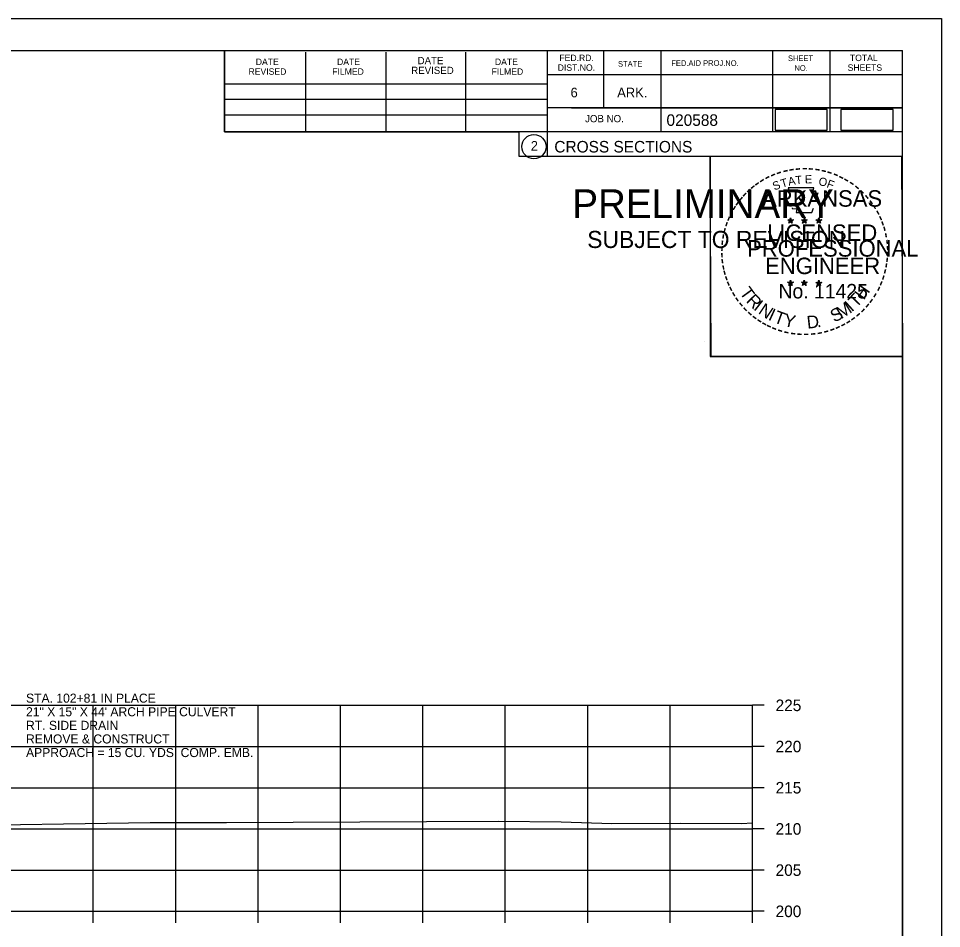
# Model space of a CAD drawing. Extents: x 1368968 to 1369915, y 377395 to 380381.
# Drawn here: x 1369189.1 to 1369301.1, y 378150.6 to 378261 of the extents above; entities that cross this region are included whole.
import ezdxf

# ---------------------------------------------------------------- set-up
doc = ezdxf.new("R2010")
doc.units = 0
for name, color, linetype in [('Default', 7, 'Continuous'), ('S_BREAKLINE_ANNOT', 7, 'Continuous'), ('S_BRIDGE', 7, 'Continuous'), ('S_BRIDGE_ANNOT', 7, 'Continuous'), ('S_BUILDING_ANNOT', 7, 'Continuous'), ('S_CAL_CORNER', 7, 'Continuous'), ('S_CTL_TABLE', 7, 'Continuous'), ('S_DITCHLINE_ANNOT', 7, 'Continuous'), ('S_DROP_INLET', 7, 'Continuous')]:
    doc.layers.add(name, color=color, linetype=linetype)

msp = doc.modelspace()

# ---------------------------------------------------------------- linework, layer by layer
at = {"layer": 'Default'}
for points in [[(1369280.87, 378247.49), (1369287.2, 378247.49), (1369287.2, 378250.01), (1369280.87, 378250.01)], [(1369288.84, 378247.47), (1369295.18, 378247.47), (1369295.18, 378249.99), (1369288.84, 378249.99)]]:
    msp.add_lwpolyline(points, close=True, dxfattribs=at)
at = {"layer": 'S_BREAKLINE_ANNOT'}
for p, q in [((1369278.13, 378152.69), (1369278.13, 378177.69)), ((1369279.53, 378177.69), (1369278.13, 378177.69)), ((1369279.53, 378172.69), (1369278.13, 378172.69)), ((1369279.53, 378167.69), (1369278.13, 378167.69)), ((1369279.53, 378162.69), (1369278.13, 378162.69)), ((1369279.53, 378157.69), (1369278.13, 378157.69)), ((1368998.13, 378152.69), (1369278.13, 378152.69)), ((1369198.13, 378151.29), (1369198.13, 378152.69)), ((1369208.13, 378151.29), (1369208.13, 378152.69)), ((1369218.13, 378151.29), (1369218.13, 378152.69)), ((1369228.13, 378151.29), (1369228.13, 378152.69)), ((1369238.13, 378151.29), (1369238.13, 378152.69)), ((1369248.13, 378151.29), (1369248.13, 378152.69)), ((1369258.13, 378151.29), (1369258.13, 378152.69)), ((1369268.13, 378151.29), (1369268.13, 378152.69)), ((1369278.13, 378151.29), (1369278.13, 378152.69)), ((1369279.53, 378152.69), (1369278.13, 378152.69))]:
    msp.add_line(p, q, dxfattribs=at)
at = {"layer": 'S_BRIDGE_ANNOT'}
for p, q in [((1368980.13, 378257.15), (1369296.31, 378257.15)), ((1369214.05, 378247.27), (1369214.05, 378257.15)), ((1369223.91, 378247.27), (1369223.91, 378256.95)), ((1369233.67, 378247.27), (1369233.67, 378256.95)), ((1369243.35, 378247.27), (1369243.35, 378256.95)), ((1369253.21, 378257.15), (1369253.21, 378244.35)), ((1369260.05, 378257.15), (1369260.05, 378250.21)), ((1369266.99, 378257.15), (1369266.99, 378247.27)), ((1369280.57, 378257.15), (1369280.57, 378247.27)), ((1369287.51, 378257.15), (1369287.51, 378247.27)), ((1369296.31, 378051.69), (1369296.31, 378257.15)), ((1369296.31, 378254.21), (1369253.21, 378254.21)), ((1369296.31, 378254.23), (1369296.31, 378254.23)), ((1369214.05, 378253.13), (1369253.21, 378253.13)), ((1369214.05, 378251.27), (1369253.21, 378251.27)), ((1369296.31, 378250.21), (1369253.21, 378250.21)), ((1369256.17, 378250.21), (1369296.31, 378250.21)), ((1369214.05, 378247.27), (1369214.05, 378249.33)), ((1369214.05, 378249.33), (1369253.21, 378249.33)), ((1369296.31, 378247.27), (1369214.05, 378247.27)), ((1369253.21, 378244.35), (1369296.31, 378244.35))]:
    msp.add_line(p, q, dxfattribs=at)
msp.add_circle((1369251.6, 378245.49), 1.47, dxfattribs=at)
at = {"layer": 'S_BUILDING_ANNOT'}
for p, q in [((1369282.4, 378236.61), (1369282.75, 378236.5)), ((1369282.4, 378236.61), (1369282.65, 378236.56)), ((1369282.4, 378236.61), (1369282.64, 378236.48)), ((1369282.53, 378236.2), (1369282.75, 378236.5)), ((1369282.53, 378236.2), (1369282.66, 378236.44)), ((1369282.53, 378236.2), (1369282.75, 378236.42)), ((1369282.75, 378236.86), (1369282.71, 378236.61)), ((1369282.75, 378236.5), (1369282.75, 378236.86)), ((1369282.75, 378236.86), (1369282.8, 378236.61)), ((1369283.09, 378236.61), (1369282.75, 378236.5)), ((1369282.96, 378236.2), (1369282.75, 378236.5)), ((1369282.96, 378236.2), (1369282.75, 378236.41)), ((1369283.09, 378236.61), (1369282.81, 378236.56)), ((1369282.96, 378236.2), (1369282.82, 378236.49)), ((1369283.09, 378236.61), (1369282.89, 378236.5)), ((1369284.07, 378236.61), (1369284.42, 378236.5)), ((1369284.07, 378236.61), (1369284.32, 378236.56)), ((1369284.07, 378236.61), (1369284.31, 378236.48)), ((1369284.2, 378236.2), (1369284.42, 378236.5)), ((1369284.2, 378236.2), (1369284.33, 378236.44)), ((1369284.2, 378236.2), (1369284.42, 378236.42)), ((1369284.42, 378236.86), (1369284.38, 378236.61)), ((1369284.42, 378236.5), (1369284.42, 378236.86)), ((1369284.42, 378236.86), (1369284.47, 378236.61)), ((1369284.76, 378236.61), (1369284.42, 378236.5)), ((1369284.63, 378236.2), (1369284.42, 378236.5)), ((1369284.63, 378236.2), (1369284.42, 378236.41)), ((1369284.76, 378236.61), (1369284.48, 378236.56)), ((1369284.63, 378236.2), (1369284.49, 378236.49)), ((1369284.76, 378236.61), (1369284.56, 378236.5)), ((1369285.83, 378236.59), (1369286.18, 378236.48)), ((1369285.83, 378236.59), (1369286.09, 378236.55)), ((1369285.83, 378236.59), (1369286.07, 378236.47)), ((1369285.97, 378236.19), (1369286.18, 378236.48)), ((1369285.97, 378236.19), (1369286.09, 378236.43)), ((1369285.97, 378236.19), (1369286.18, 378236.4)), ((1369286.18, 378236.85), (1369286.14, 378236.6)), ((1369286.18, 378236.48), (1369286.18, 378236.85)), ((1369286.18, 378236.85), (1369286.23, 378236.6)), ((1369286.53, 378236.59), (1369286.18, 378236.48)), ((1369286.39, 378236.19), (1369286.18, 378236.48)), ((1369286.39, 378236.19), (1369286.18, 378236.4)), ((1369286.53, 378236.59), (1369286.24, 378236.55)), ((1369286.39, 378236.19), (1369286.26, 378236.48)), ((1369286.53, 378236.59), (1369286.32, 378236.49)), ((1369282.39, 378229.03), (1369282.74, 378228.92)), ((1369282.39, 378229.03), (1369282.65, 378228.99)), ((1369282.39, 378229.03), (1369282.63, 378228.91)), ((1369282.53, 378228.63), (1369282.74, 378228.92)), ((1369282.53, 378228.63), (1369282.65, 378228.87)), ((1369282.53, 378228.63), (1369282.74, 378228.84)), ((1369282.74, 378229.29), (1369282.7, 378229.04)), ((1369282.74, 378228.92), (1369282.74, 378229.29)), ((1369282.74, 378229.29), (1369282.79, 378229.04)), ((1369283.09, 378229.03), (1369282.74, 378228.92)), ((1369282.96, 378228.63), (1369282.74, 378228.92)), ((1369282.96, 378228.63), (1369282.74, 378228.84)), ((1369283.09, 378229.03), (1369282.8, 378228.98)), ((1369282.96, 378228.63), (1369282.82, 378228.92)), ((1369283.09, 378229.03), (1369282.89, 378228.93)), ((1369284.06, 378229.03), (1369284.41, 378228.92)), ((1369284.06, 378229.03), (1369284.32, 378228.99)), ((1369284.06, 378229.03), (1369284.3, 378228.91)), ((1369284.2, 378228.63), (1369284.41, 378228.92)), ((1369284.2, 378228.63), (1369284.32, 378228.87)), ((1369284.2, 378228.63), (1369284.41, 378228.84)), ((1369284.41, 378229.29), (1369284.37, 378229.04)), ((1369284.41, 378228.92), (1369284.41, 378229.29)), ((1369284.41, 378229.29), (1369284.46, 378229.04)), ((1369284.76, 378229.03), (1369284.41, 378228.92)), ((1369284.63, 378228.63), (1369284.41, 378228.92)), ((1369284.63, 378228.63), (1369284.41, 378228.84)), ((1369284.76, 378229.03), (1369284.47, 378228.98)), ((1369284.63, 378228.63), (1369284.49, 378228.92)), ((1369284.76, 378229.03), (1369284.56, 378228.93)), ((1369285.83, 378229.02), (1369286.18, 378228.91)), ((1369285.83, 378229.02), (1369286.08, 378228.98)), ((1369285.83, 378229.02), (1369286.07, 378228.9)), ((1369285.96, 378228.62), (1369286.18, 378228.91)), ((1369285.96, 378228.62), (1369286.09, 378228.86)), ((1369285.96, 378228.62), (1369286.18, 378228.83)), ((1369286.18, 378229.28), (1369286.14, 378229.03)), ((1369286.18, 378228.91), (1369286.18, 378229.28)), ((1369286.18, 378229.28), (1369286.23, 378229.03)), ((1369286.53, 378229.02), (1369286.18, 378228.91)), ((1369286.39, 378228.62), (1369286.18, 378228.91)), ((1369286.39, 378228.62), (1369286.18, 378228.83)), ((1369286.53, 378229.02), (1369286.24, 378228.97)), ((1369286.39, 378228.62), (1369286.26, 378228.91)), ((1369286.53, 378229.02), (1369286.32, 378228.92))]:
    msp.add_line(p, q, dxfattribs=at)
for points in [[(1369282.44, 378240.48), (1369282.71, 378239.66)], [(1369285.95, 378239.56), (1369286.09, 378239.85), (1369285.41, 378239.82), (1369285.56, 378240.48), (1369282.44, 378240.48)], [(1369282.93, 378238.06), (1369282.93, 378237.97), (1369283.49, 378237.96), (1369283.44, 378237.48), (1369285.31, 378237.48), (1369285.51, 378238.02)], [(1369282.75, 378236.86), (1369282.96, 378236.2), (1369282.4, 378236.61), (1369283.09, 378236.61), (1369282.53, 378236.2), (1369282.75, 378236.86)], [(1369284.42, 378236.86), (1369284.63, 378236.2), (1369284.07, 378236.61), (1369284.76, 378236.61), (1369284.2, 378236.2), (1369284.42, 378236.86)], [(1369286.18, 378236.85), (1369286.39, 378236.19), (1369285.83, 378236.59), (1369286.53, 378236.59), (1369285.97, 378236.19), (1369286.18, 378236.85)], [(1369282.74, 378229.29), (1369282.96, 378228.63), (1369282.39, 378229.03), (1369283.09, 378229.03), (1369282.53, 378228.63), (1369282.74, 378229.29)], [(1369284.41, 378229.29), (1369284.63, 378228.63), (1369284.06, 378229.03), (1369284.76, 378229.03), (1369284.2, 378228.63), (1369284.41, 378229.29)], [(1369286.18, 378229.28), (1369286.39, 378228.62), (1369285.83, 378229.02), (1369286.53, 378229.02), (1369285.96, 378228.62), (1369286.18, 378229.28)]]:
    msp.add_lwpolyline(points, dxfattribs=at)
for centre, radius in [((1369282.75, 378236.49), 0.172), ((1369282.75, 378236.49), 0.145), ((1369282.75, 378236.49), 0.116), ((1369282.75, 378236.49), 0.0991), ((1369282.75, 378236.49), 0.0747), ((1369282.75, 378236.49), 0.0495), ((1369282.75, 378236.49), 0.0296), ((1369284.42, 378236.49), 0.172), ((1369284.42, 378236.49), 0.145), ((1369284.42, 378236.49), 0.116), ((1369284.42, 378236.49), 0.0991), ((1369284.42, 378236.49), 0.0747), ((1369284.42, 378236.49), 0.0495), ((1369284.42, 378236.49), 0.0296), ((1369286.18, 378236.48), 0.172), ((1369286.18, 378236.48), 0.145), ((1369286.18, 378236.48), 0.116), ((1369286.18, 378236.48), 0.0991), ((1369286.18, 378236.48), 0.0747), ((1369286.18, 378236.48), 0.0495), ((1369286.18, 378236.48), 0.0296), ((1369282.74, 378228.92), 0.172), ((1369282.74, 378228.92), 0.145), ((1369282.74, 378228.92), 0.116), ((1369282.74, 378228.92), 0.0991), ((1369282.74, 378228.92), 0.0747), ((1369282.74, 378228.92), 0.0495), ((1369282.74, 378228.92), 0.0296), ((1369284.41, 378228.92), 0.172), ((1369284.41, 378228.92), 0.145), ((1369284.41, 378228.92), 0.116), ((1369284.41, 378228.92), 0.0991), ((1369284.41, 378228.92), 0.0747), ((1369284.41, 378228.92), 0.0495), ((1369284.41, 378228.92), 0.0296), ((1369286.18, 378228.91), 0.172), ((1369286.18, 378228.91), 0.145), ((1369286.18, 378228.91), 0.116), ((1369286.18, 378228.91), 0.0991), ((1369286.18, 378228.91), 0.0747), ((1369286.18, 378228.91), 0.0495), ((1369286.18, 378228.91), 0.0296)]:
    msp.add_circle(centre, radius, dxfattribs=at)
at = {"layer": 'S_CTL_TABLE'}
msp.add_lwpolyline([(1369178.76, 378163.06), (1369205.02, 378163.48), (1369205.6, 378163.48), (1369214.3, 378163.46), (1369238.55, 378163.61), (1369247.27, 378163.63), (1369254.92, 378163.56), (1369261.07, 378163.34), (1369269.43, 378163.38), (1369276.78, 378163.36), (1369278.13, 378163.44)], dxfattribs=at)
at = {"layer": 'S_DITCHLINE_ANNOT'}
for p, q in [((1368998.13, 378177.69), (1369278.13, 378177.69)), ((1369198.13, 378152.69), (1369198.13, 378177.69)), ((1369208.13, 378152.69), (1369208.13, 378177.69)), ((1369218.13, 378152.69), (1369218.13, 378177.69)), ((1369228.13, 378152.69), (1369228.13, 378177.69)), ((1369238.13, 378152.69), (1369238.13, 378177.69)), ((1369248.13, 378152.69), (1369248.13, 378177.69)), ((1369258.13, 378152.69), (1369258.13, 378177.69)), ((1369268.13, 378152.69), (1369268.13, 378177.69)), ((1369278.13, 378152.69), (1369278.13, 378177.69)), ((1368998.13, 378172.69), (1369278.13, 378172.69)), ((1368998.13, 378167.69), (1369278.13, 378167.69)), ((1368998.13, 378162.69), (1369278.13, 378162.69)), ((1368998.13, 378157.69), (1369278.13, 378157.69)), ((1368998.13, 378152.69), (1369278.13, 378152.69))]:
    msp.add_line(p, q, dxfattribs=at)
at = {"layer": 'S_DROP_INLET'}
for p, q in [((1368967.73, 378261.05), (1369301.07, 378261.05)), ((1369272.35, 378221.9), (1369272.35, 378221.9))]:
    msp.add_line(p, q, dxfattribs=at)
for points in [[(1368967.73, 378261.05), (1369301.07, 378261.05), (1369301.07, 378047.71), (1368967.73, 378047.71)], [(1369214.05, 378257.15), (1369214.05, 378247.27), (1369249.79, 378247.27), (1369249.79, 378244.35), (1369272.99, 378244.35), (1369272.99, 378220.02), (1369296.31, 378220.02), (1369296.31, 378051.69), (1368980.13, 378051.69), (1368980.13, 378257.15)], [(1369272.99, 378244.35), (1369296.19, 378244.35), (1369296.31, 378220.02), (1369273.11, 378220.02)]]:
    msp.add_lwpolyline(points, close=True, dxfattribs=at)

# ---------------------------------------------------------------- texts
at = {"layer": 'Default'}
for s, p in [('STA. 102+81 IN PLACE', (1369189.97, 378178.01)), ('21" X 15" X 44\' ARCH PIPE CULVERT', (1369189.97, 378176.36)), ('RT. SIDE DRAIN', (1369189.97, 378174.71)), ('REMOVE & CONSTRUCT ', (1369189.97, 378173.06)), ('APPROACH = 15 CU. YDS. COMP. EMB.', (1369189.97, 378171.41))]:
    msp.add_text(s, height=1.1, dxfattribs=at).set_placement(p)
at = {"layer": 'S_BRIDGE'}
for s, p in [('225', (1369280.93, 378176.99)), ('220', (1369280.93, 378171.99)), ('215', (1369280.93, 378166.99)), ('210', (1369280.93, 378161.99)), ('205', (1369280.93, 378156.99)), ('200', (1369280.93, 378151.99))]:
    msp.add_text(s, height=1.4, dxfattribs=at).set_placement(p)
at = {"layer": 'S_BRIDGE_ANNOT'}
for s, height, p in [('DATE', 0.879, (1369237.49, 378255.49)), ('FED.RD.', 0.782, (1369254.69, 378255.87)), ('SHEET', 0.684, (1369282.43, 378255.87)), ('TOTAL', 0.782, (1369289.95, 378255.87)), ('DATE', 0.782, (1369217.85, 378255.39)), ('DATE', 0.782, (1369227.71, 378255.39)), ('REVISED', 0.879, (1369236.71, 378254.31)), ('DATE', 0.782, (1369246.87, 378255.39)), ('DIST.NO.', 0.782, (1369254.49, 378254.69)), ('STATE', 0.684, (1369261.81, 378255.19)), ('FED.AID PROJ.NO.', 0.684, (1369268.27, 378255.29)), ('NO.', 0.684, (1369283.21, 378254.69)), ('SHEETS', 0.782, (1369289.67, 378254.69)), ('REVISED', 0.782, (1369216.97, 378254.21)), ('FILMED', 0.782, (1369227.13, 378254.21)), ('FILMED', 0.782, (1369246.47, 378254.21)), ('6', 1.17, (1369256.05, 378251.47)), ('ARK.', 1.172, (1369261.71, 378251.47)), ('JOB NO.', 0.879, (1369257.81, 378248.45)), ('020588', 1.4, (1369267.69, 378248.01)), ('CROSS SECTIONS', 1.4, (1369254.08, 378244.78)), ('2', 1.17, (1369251.22, 378245))]:
    msp.add_text(s, height=height, rotation=360, dxfattribs=at).set_placement(p)
at = {"layer": 'S_BUILDING_ANNOT'}
for s, height, rotation, p in [('-', 1.6, 5.8968, (1369283.34, 378242.12)), ('-', 1.6, 0.1862, (1369284.12, 378242.2)), ('-', 1.6, 357.743, (1369284.84, 378242.18)), ('-', 1.6, 28.7918, (1369279.92, 378241.03)), ('-', 1.6, 24.3072, (1369280.55, 378241.34)), ('-', 1.6, 19.1761, (1369281.19, 378241.61)), ('-', 1.6, 13.6301, (1369281.94, 378241.85)), ('A', 1, 11.2132, (1369282.53, 378240.74)), ('-', 1.6, 10.2193, (1369282.62, 378242.01)), ('T', 1, 6.0228, (1369283.38, 378240.91)), ('E', 1, 0.8323, (1369284.49, 378241.02)), ('-', 1.6, 352.1617, (1369285.58, 378242.13)), ('O', 1, 350.4515, (1369286.09, 378240.81)), ('-', 1.6, 347.2049, (1369286.3, 378242.01)), ('-', 1.6, 342.3362, (1369286.94, 378241.86)), ('-', 1.6, 337.8551, (1369287.67, 378241.64)), ('-', 1.6, 334.1211, (1369288.3, 378241.36)), ('-', 1.6, 38.9507, (1369278.27, 378239.88)), ('-', 1.6, 36.2317, (1369278.75, 378240.26)), ('-', 1.6, 34.0636, (1369279.32, 378240.66)), ('S', 1, 21.594, (1369280.79, 378240.16)), ('T', 1, 16.4036, (1369281.71, 378240.49)), ('F', 1, 340.0707, (1369287.05, 378240.58)), ('-', 1.6, 329.6409, (1369288.88, 378241.08)), ('-', 1.6, 325.8627, (1369289.53, 378240.72)), ('-', 1.6, 320.5297, (1369290.14, 378240.29)), ('-', 1.6, 48.423, (1369277.39, 378238.99)), ('-', 1.6, 42.9622, (1369277.84, 378239.47)), ('ARKANSAS', 2, 360, (1369279.29, 378238.2)), ('-', 1.6, 315.5786, (1369290.73, 378239.81)), ('-', 1.6, 309.8797, (1369291.3, 378239.26)), ('-', 1.6, 54.2325, (1369276.57, 378237.93)), ('-', 1.6, 50.6142, (1369276.99, 378238.5)), ('-', 1.6, 306.6522, (1369291.83, 378238.65)), ('-', 1.4, 303.6753, (1369292.31, 378238.09)), ('-', 1.6, 62.8713, (1369275.93, 378236.79)), ('-', 1.6, 58.0706, (1369276.25, 378237.41)), ('-', 1.6, 299.6684, (1369292.63, 378237.48)), ('-', 1.6, 72.3945, (1369275.46, 378235.55)), ('-', 1.6, 67.7743, (1369275.68, 378236.18)), ('DWB', 0.01, 360, (1369282.73, 378236.49)), ('DWB', 0.01, 360, (1369284.4, 378236.49)), ('DWB', 0.01, 360, (1369286.17, 378236.48)), ('-', 1.6, 294.6628, (1369292.96, 378236.87)), ('-', 1.6, 290.5728, (1369293.21, 378236.29)), ('-', 1.6, 75.461, (1369275.26, 378234.84)), ('LICENSED', 2, 360, (1369279.89, 378234.05)), ('-', 1.6, 285.1233, (1369293.45, 378235.71)), ('-', 1.6, 280.5493, (1369293.65, 378234.97)), ('-', 1.6, 85.1863, (1369275.05, 378233.43)), ('-', 1.6, 81.2013, (1369275.13, 378234.13)), ('PROFESSIONAL', 2, 360, (1369277.47, 378232.14)), ('-', 1.6, 276.5962, (1369293.81, 378234.2)), ('-', 1.6, 89.0622, (1369275.03, 378232.73)), ('-', 1.6, 274.3301, (1369293.87, 378233.48)), ('-', 1.6, 94.1959, (1369275.06, 378232.01)), ('-', 1.6, 98.9479, (1369275.13, 378231.34)), ('ENGINEER', 2, 360, (1369279.65, 378230.02)), ('-', 1.6, 263.5172, (1369293.89, 378232.18)), ('-', 1.6, 269.9407, (1369293.9, 378232.85)), ('-', 1.6, 101.7149, (1369275.27, 378230.61)), ('-', 1.6, 255.7626, (1369293.7, 378230.85)), ('-', 1.6, 260.9953, (1369293.81, 378231.53)), ('-', 1.6, 105.4578, (1369275.43, 378230.01)), ('-', 1.6, 109.0874, (1369275.65, 378229.38)), ('-', 1.6, 252.8681, (1369293.52, 378230.13)), ('-', 1.6, 114.0643, (1369275.9, 378228.79)), ('-', 1.6, 115.7289, (1369276.2, 378228.17)), ('T', 1.54, 306.0406, (1369276.5, 378227.76)), ('No. 11425', 1.757, 360, (1369281.28, 378227.07)), ('DWB', 0.01, 360, (1369282.73, 378228.92)), ('DWB', 0.01, 360, (1369284.4, 378228.92)), ('DWB', 0.01, 360, (1369286.17, 378228.91)), ('H', 1.54, 54.6088, (1369291.62, 378226.8)), ('-', 1.6, 244.6197, (1369293.04, 378228.83)), ('-', 1.6, 247.8887, (1369293.3, 378229.46)), ('-', 1.6, 120.4471, (1369276.56, 378227.58)), ('-', 1.6, 125.8934, (1369276.96, 378227.02)), ('R', 1.54, 314.005, (1369277.27, 378226.71)), ('T', 1.54, 46.6444, (1369290.73, 378225.85)), ('-', 1.6, 239.0712, (1369292.64, 378228.07)), ('-', 1.6, 130.7181, (1369277.43, 378226.47)), ('I', 1.54, 321.9694, (1369278.17, 378225.78)), ('N', 1.54, 326.5002, (1369278.73, 378225.31)), ('M', 1.54, 32.6563, (1369288.89, 378224.53)), ('I', 1.54, 42.1136, (1369290.17, 378225.37)), ('-', 1.6, 231.2538, (1369291.81, 378226.86)), ('-', 1.6, 233.8452, (1369292.24, 378227.42)), ('-', 1.6, 134.2238, (1369277.94, 378225.92)), ('-', 1.6, 138.9338, (1369278.47, 378225.46)), ('-', 1.6, 144.6463, (1369279.02, 378225.05)), ('I', 1.54, 335.3603, (1369279.94, 378224.52)), ('T', 1.54, 339.8912, (1369280.6, 378224.2)), ('Y', 1.54, 347.8556, (1369281.82, 378223.75)), ('D', 1.54, 6.3969, (1369284.8, 378223.39)), ('S', 1.54, 26.9312, (1369288.05, 378224.12)), ('-', 1.6, 221.0851, (1369290.81, 378225.78)), ('-', 1.6, 225.7653, (1369291.33, 378226.29)), ('-', 1.6, 148.0898, (1369279.59, 378224.68)), ('-', 1.6, 151.5704, (1369280.16, 378224.36)), ('-', 1.6, 154.6002, (1369280.69, 378224.11)), ('.', 1.54, 13.7642, (1369286, 378223.52)), ('-', 1.6, 207.3568, (1369289.17, 378224.58)), ('-', 1.6, 212.2491, (1369289.73, 378224.92)), ('-', 1.6, 215.7363, (1369290.26, 378225.31)), ('-', 1.6, 158.5612, (1369281.31, 378223.86)), ('-', 1.6, 162.7983, (1369282, 378223.64)), ('-', 1.6, 167.5555, (1369282.71, 378223.48)), ('-', 1.6, 173.1155, (1369283.48, 378223.37)), ('-', 1.6, 176.5183, (1369284.23, 378223.32)), ('-', 1.6, 181.5918, (1369284.98, 378223.34)), ('-', 1.6, 185.8167, (1369285.79, 378223.41)), ('-', 1.6, 191.2858, (1369286.52, 378223.54)), ('-', 1.6, 195.4743, (1369287.25, 378223.74)), ('-', 1.6, 200.7184, (1369287.93, 378223.99)), ('-', 1.6, 204.2516, (1369288.55, 378224.26))]:
    msp.add_text(s, height=height, rotation=rotation, dxfattribs=at).set_placement(p)
at = {"layer": 'S_CAL_CORNER'}
for s, height, p in [('PRELIMINARY', 3.5, (1369256.26, 378236.81)), ('DWB', 0.01, (1369257.01, 378238.66)), ('SUBJECT TO REVISION', 2.0751, (1369258.07, 378233.19))]:
    msp.add_text(s, height=height, rotation=360, dxfattribs=at).set_placement(p)

doc.saveas('drawing.dxf')
